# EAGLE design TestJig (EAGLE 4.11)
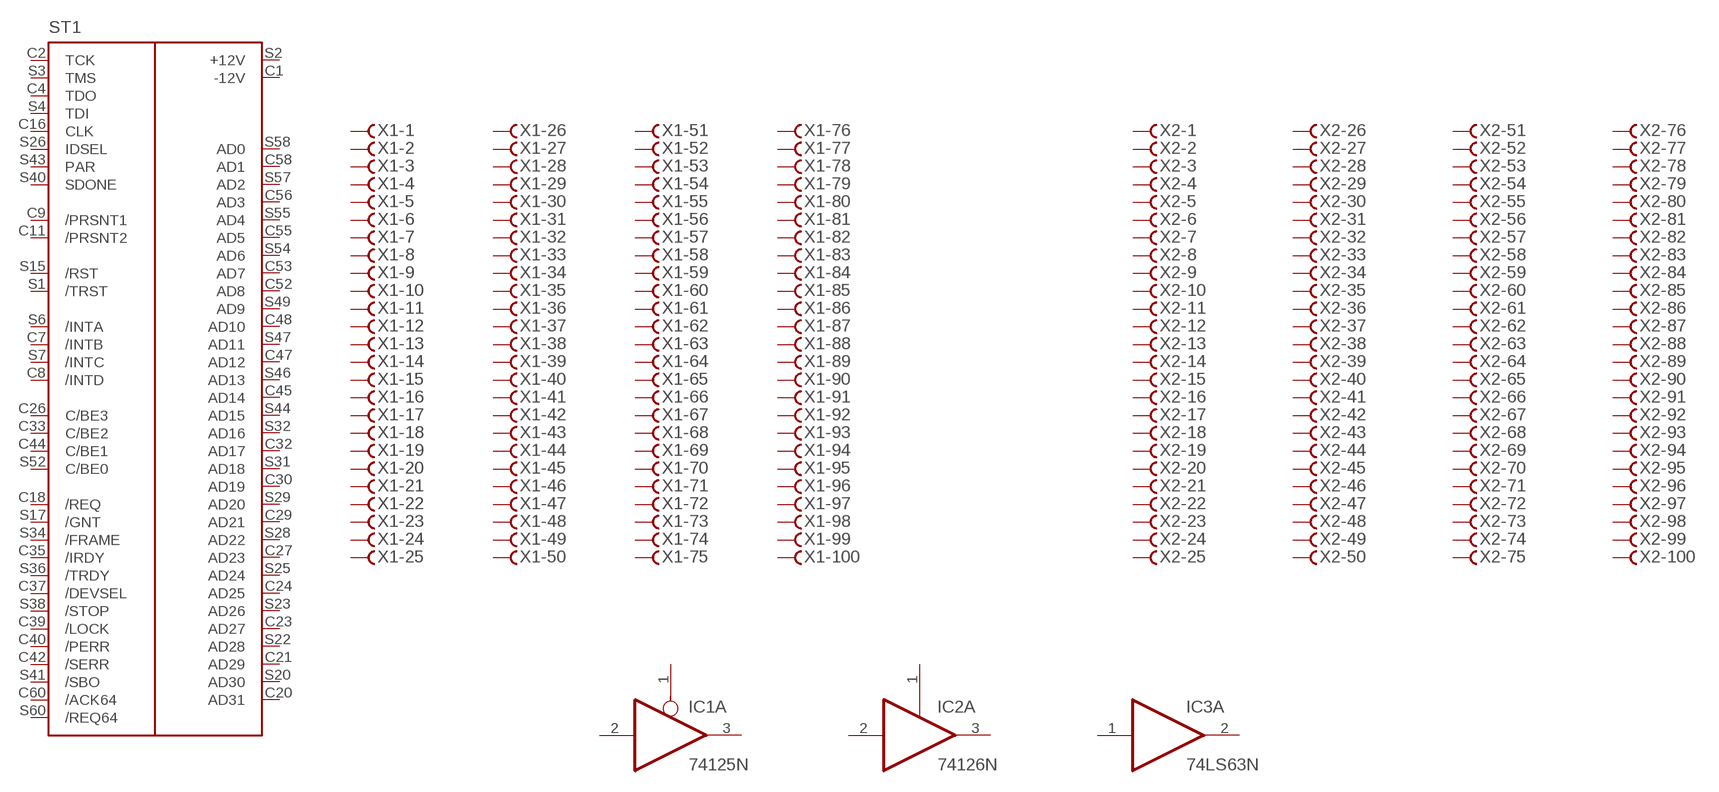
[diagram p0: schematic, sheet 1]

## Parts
IC1  74125N  [DIL14]
IC2  74126N  [DIL14]
IC3  74LS63N  [DIL14]
ST1  PCI2-SLOT  [PCI_BRD]
X1  HFR100RA  [HFR100RA]
X2  HXR100ST  [HXR100ST]
Unconnected: IC1.1(A:OE) IC1.2(A:I) IC1.3(A:O) IC1.4(B:OE) IC1.5(B:I) IC1.6(B:O) IC1.8(C:O) IC1.9(C:I) IC1.10(C:OE) IC1.11(D:O) IC1.12(D:I) IC1.13(D:OE) IC2.1(A:OE) IC2.2(A:I) IC2.3(A:O) IC2.4(B:OE) IC2.5(B:I) IC2.6(B:O) IC2.8(C:O) IC2.9(C:I) IC2.10(C:OE) IC2.11(D:O) IC2.12(D:I) IC2.13(D:OE) IC3.1(A:I) IC3.2(A:O) IC3.3(B:O) IC3.4(B:I) IC3.5(C:I) IC3.6(C:O) IC3.8(D:O) IC3.9(D:I) IC3.10(E:I) IC3.11(E:O) IC3.12(F:O) IC3.13(F:I) ST1.C2(TCK) ST1.C4(TDO) ST1.C7(/INTB) ST1.C8(/INTD) ST1.C9(/PRSNT1) ST1.C10(NC3) ST1.C11(/PRSNT2) ST1.C14(NC4) ST1.C16(CLK) ST1.C18(/REQ) ST1.C20(AD31) ST1.C21(AD29) ST1.C23(AD27) ST1.C24(AD25) ST1.C26(C/BE3) ST1.C27(AD23) ST1.C29(AD21) ST1.C30(AD19) ST1.C32(AD17) ST1.C33(C/BE2) ST1.C35(/IRDY) ST1.C37(/DEVSEL) ST1.C39(/LOCK) ST1.C40(/PERR) ST1.C42(/SERR) ST1.C44(C/BE1) ST1.C45(AD14) ST1.C47(AD12) ST1.C48(AD10) ST1.C52(AD8) ST1.C53(AD7) ST1.C55(AD5) ST1.C56(AD3) ST1.C58(AD1) ST1.C60(/ACK64) ST1.S1(/TRST) ST1.S3(TMS) ST1.S4(TDI) ST1.S6(/INTA) ST1.S7(/INTC) ST1.S9(NC0) ST1.S11(NC5) ST1.S14(NC1) ST1.S15(/RST) ST1.S17(/GNT) ST1.S19(NC2) ST1.S20(AD30) ST1.S22(AD28) ST1.S23(AD26) ST1.S25(AD24) ST1.S26(IDSEL) ST1.S28(AD22) ST1.S29(AD20) ST1.S31(AD18) ST1.S32(AD16) ST1.S34(/FRAME) ST1.S35(GND) ST1.S36(/TRDY) ST1.S38(/STOP) ST1.S39(+3,3V) ST1.S40(SDONE) ST1.S41(/SBO) ST1.S43(PAR) ST1.S44(AD15) ST1.S46(AD13) ST1.S47(AD11) ST1.S49(AD9) ST1.S52(C/BE0) ST1.S54(AD6) ST1.S55(AD4) ST1.S57(AD2) ST1.S58(AD0) ST1.S60(/REQ64) X1.1 X1.2 X1.3 X1.4 X1.5 X1.6 X1.7 X1.8 X1.9 X1.10 X1.11 X1.12 X1.13 X1.14 X1.15 X1.16 X1.17 X1.18 X1.19 X1.20 X1.21 X1.22 X1.23 X1.24 X1.25 X1.26 X1.27 X1.28 X1.29 X1.30 X1.31 X1.32 X1.33 X1.34 X1.35 X1.36 X1.37 X1.38 X1.39 X1.40 X1.41 X1.42 X1.43 X1.44 X1.45 X1.46 X1.47 X1.48 X1.49 X1.50 X1.51 X1.52 X1.53 X1.54 X1.55 X1.56 X1.57 X1.58 X1.59 X1.60 X1.61 X1.62 X1.63 X1.64 X1.65 X1.66 X1.67 X1.68 X1.69 X1.70 X1.71 X1.72 X1.73 X1.74 X1.75 X1.76 X1.77 X1.78 X1.79 X1.80 X1.81 X1.82 X1.83 X1.84 X1.85 X1.86 X1.87 X1.88 X1.89 X1.90 X1.91 X1.92 X1.93 X1.94 X1.95 X1.96 X1.97 X1.98 X1.99 X1.100 X2.1 X2.2 X2.3 X2.4 X2.5 X2.6 X2.7 X2.8 X2.9 X2.10 X2.11 X2.12 X2.13 X2.14 X2.15 X2.16 X2.17 X2.18 X2.19 X2.20 X2.21 X2.22 X2.23 X2.24 X2.25 X2.26 X2.27 X2.28 X2.29 X2.30 X2.31 X2.32 X2.33 X2.34 X2.35 X2.36 X2.37 X2.38 X2.39 X2.40 X2.41 X2.42 X2.43 X2.44 X2.45 X2.46 X2.47 X2.48 X2.49 X2.50 X2.51 X2.52 X2.53 X2.54 X2.55 X2.56 X2.57 X2.58 X2.59 X2.60 X2.61 X2.62 X2.63 X2.64 X2.65 X2.66 X2.67 X2.68 X2.69 X2.70 X2.71 X2.72 X2.73 X2.74 X2.75 X2.76 X2.77 X2.78 X2.79 X2.80 X2.81 X2.82 X2.83 X2.84 X2.85 X2.86 X2.87 X2.88 X2.89 X2.90 X2.91 X2.92 X2.93 X2.94 X2.95 X2.96 X2.97 X2.98 X2.99 X2.100

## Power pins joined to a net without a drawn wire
+3,3V: ST1.C25(+3,3V) ST1.C31(+3,3V) ST1.C36(+3,3V) ST1.C41(+3,3V) ST1.C43(+3,3V) ST1.C54(+3,3V) ST1.S21(+3,3V) ST1.S27(+3,3V) ST1.S33(+3,3V) ST1.S45(+3,3V) ST1.S53(+3,3V)
+5V: ST1.C5(+5V) ST1.C6(+5V) ST1.C19(+5V) ST1.C59(+5V) ST1.C61(+5V) ST1.C62(+5V) ST1.S5(+5V) ST1.S8(+5V) ST1.S10(+5V) ST1.S16(+5V) ST1.S59(+5V) ST1.S61(+5V) ST1.S62(+5V)
+12V: ST1.S2(+12V)
-12V: ST1.C1(-12V)
GND: IC1.7(P:GND) IC2.7(P:GND) IC3.7(P:GND) ST1.C3(GND) ST1.C12(GND) ST1.C13(GND) ST1.C15(GND) ST1.C17(GND) ST1.C22(GND) ST1.C28(GND) ST1.C34(GND) ST1.C38(GND) ST1.C46(GND) ST1.C49(GND) ST1.C57(GND) ST1.S12(GND) ST1.S13(GND) ST1.S18(GND) ST1.S24(GND) ST1.S30(GND) ST1.S37(GND) ST1.S42(GND) ST1.S48(GND) ST1.S56(GND)
VCC: IC1.14(P:VCC) IC2.14(P:VCC) IC3.14(P:VCC)

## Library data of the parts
IC1 = 74xx-us:74*125: Quad bus BUFFER, 3-state
IC2 = 74xx-us:74*126: Quad bus BUFFER, 3-state
IC3 = 74xx-us:74*63: Hex current sensing INTERFACE gate, totem pole
ST1 = con-pc:PCI2-SLOT: PCI BOARD SHORT
X1 = con-thomas-betts:HFR100RA: THOMAS&BETTS
X2 = con-thomas-betts:HXR100ST: THOMAS&BETTS

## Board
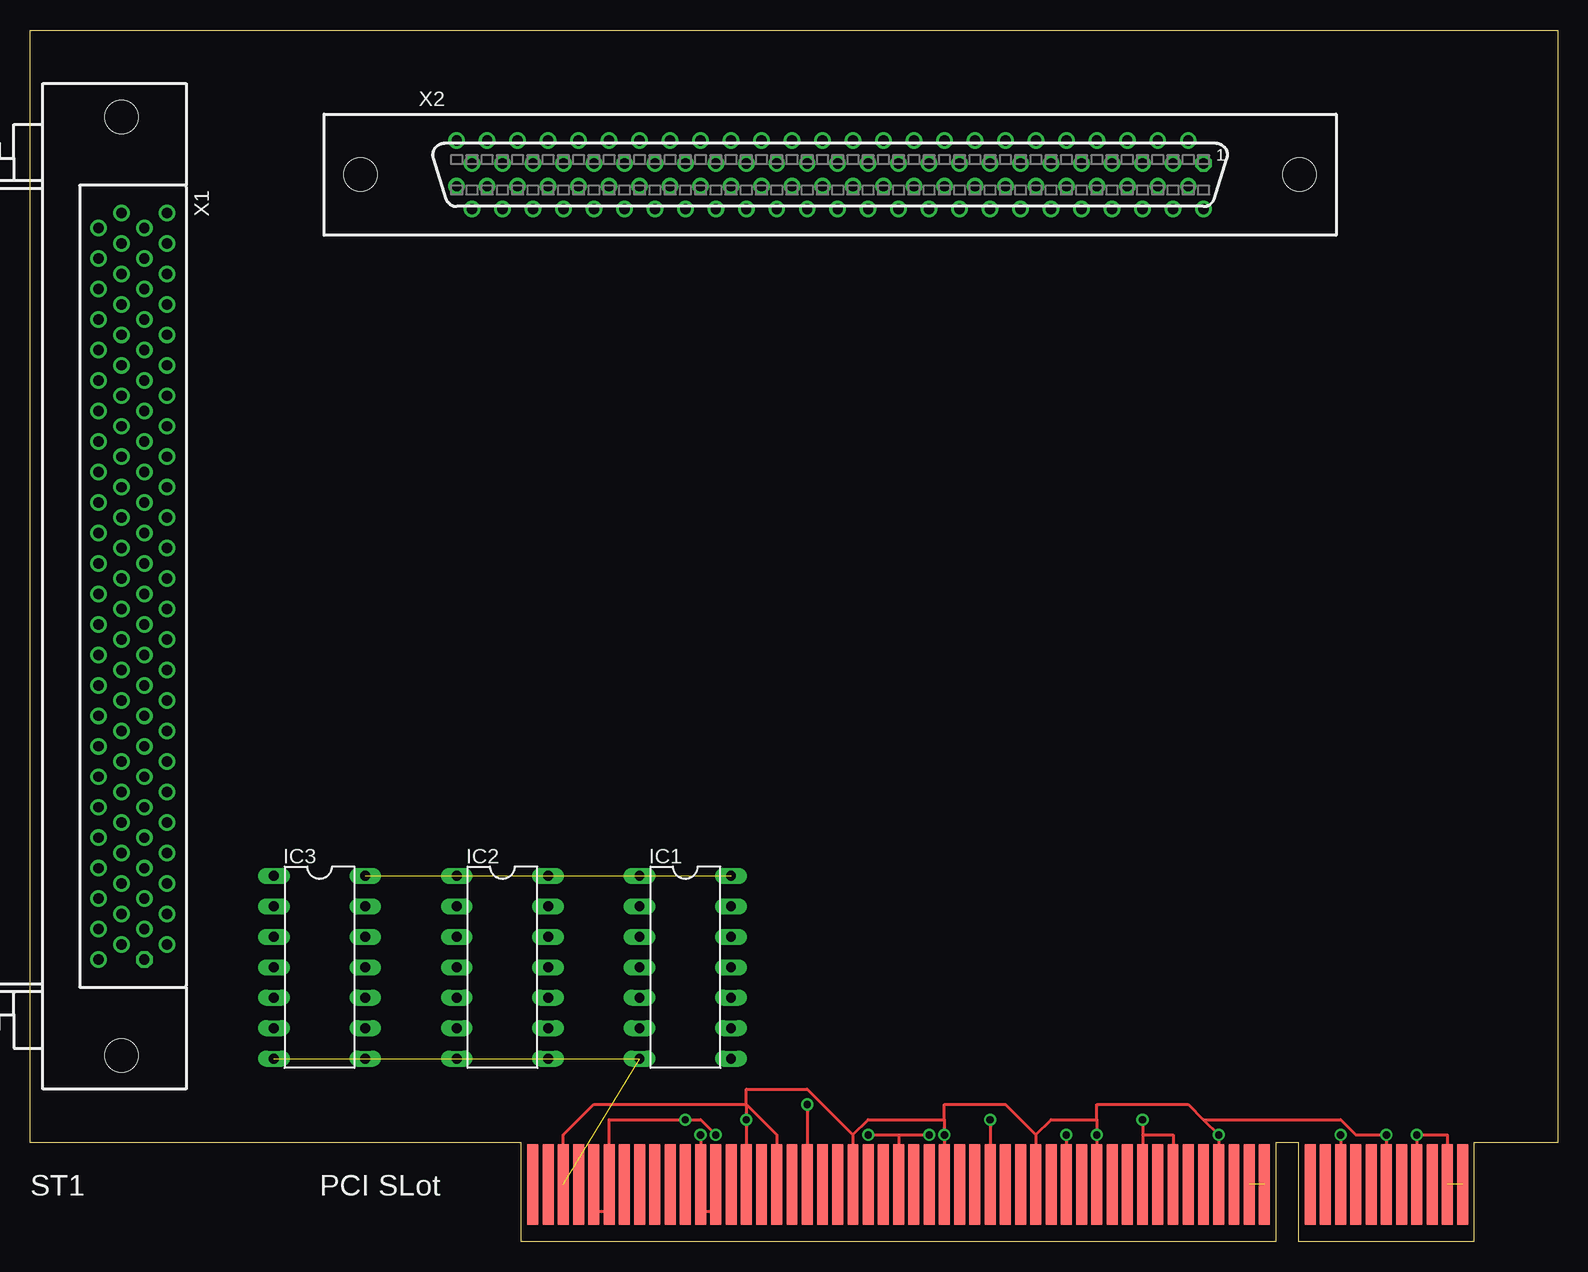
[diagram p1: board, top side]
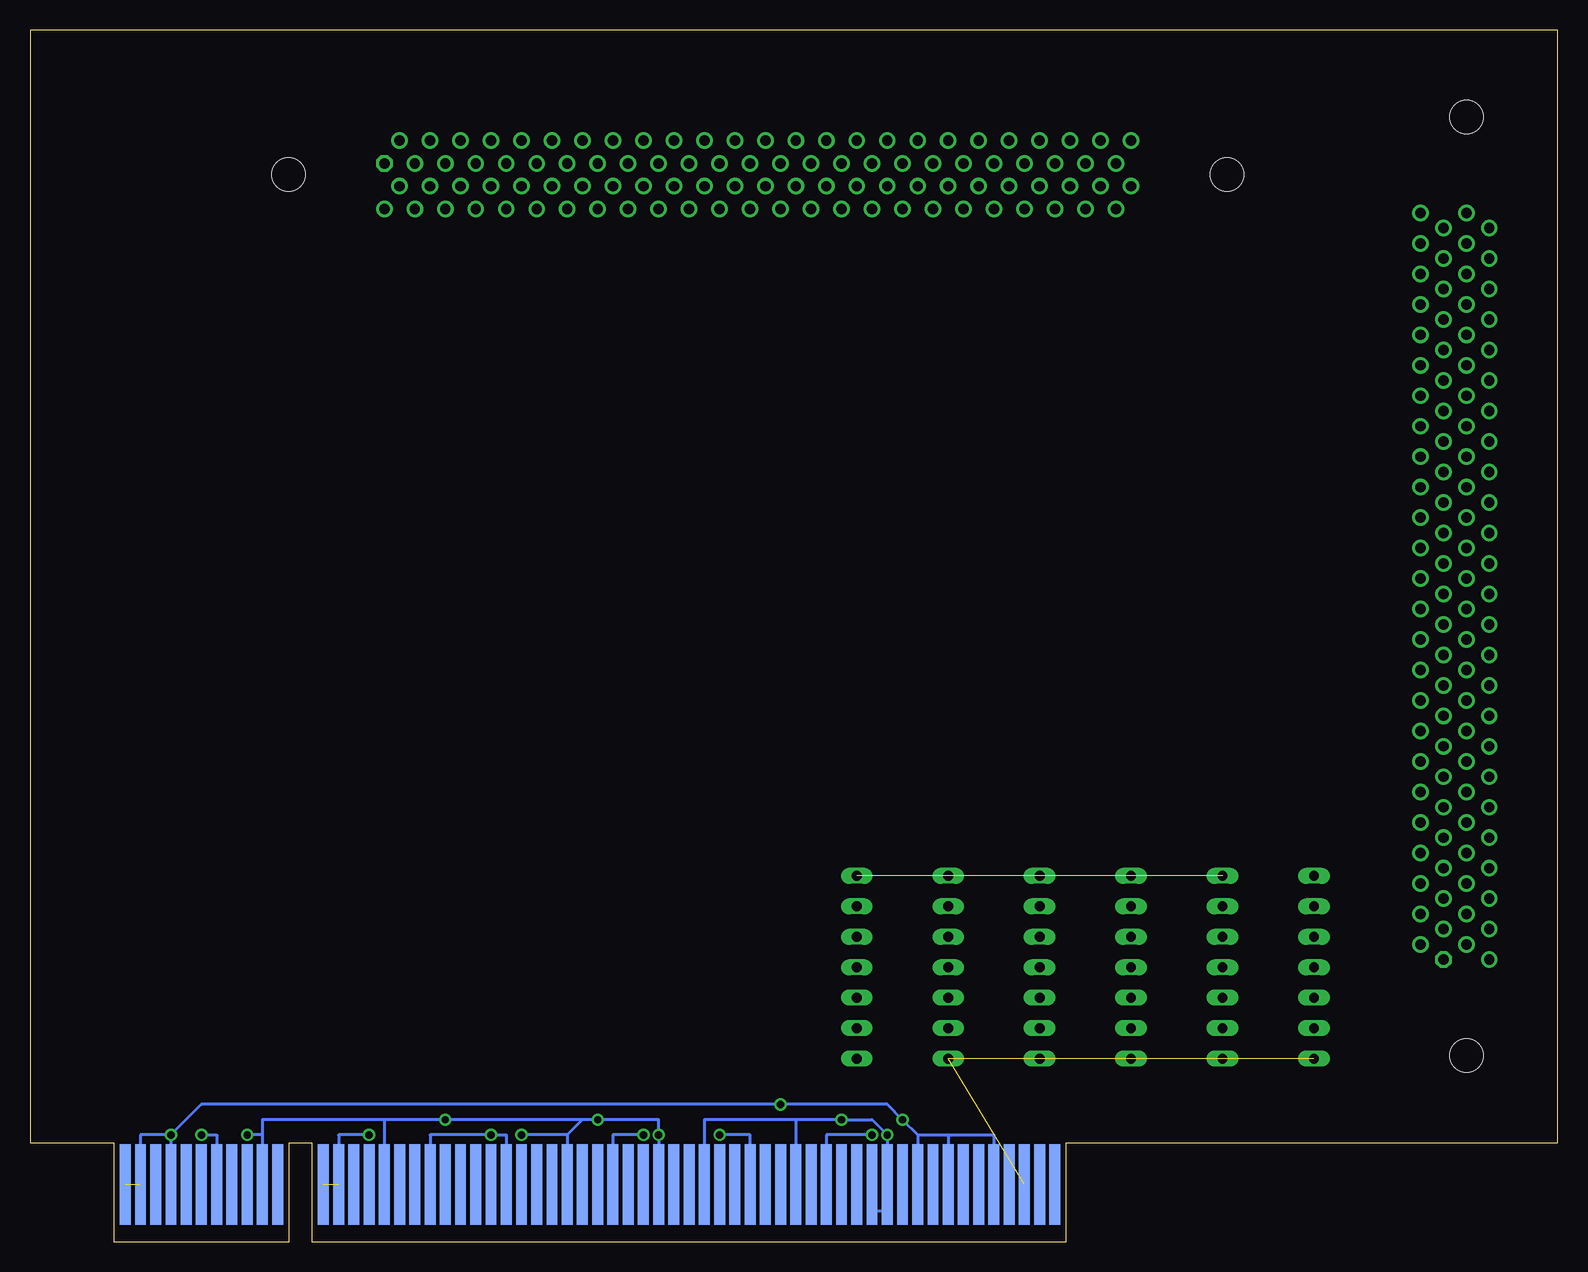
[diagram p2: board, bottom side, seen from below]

Size 127.32 x 100.97 mm. Coordinates in mm from the lower left corner, seen from the top.
Copper layers (1*16): Top 0.035mm / dielectric 1.5mm / Bottom 0.035mm
Design rules "10mils": minimum track width 10mil, minimum drill 24mil, track to track 10mil, track to pad 10mil, pad to pad 10mil, via to via 10mil, smd to smd 10mil, copper to edge 40mil, drill to drill 10mil, minimum pad ring 10mil, minimum via ring 8mil, stop-mask expansion 0mil, vias tented up to drill 0mil, thermal gap 10mil

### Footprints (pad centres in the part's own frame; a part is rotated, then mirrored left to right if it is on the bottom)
DIL14 = drill 0.813 long: 1 -7.62,-3.81; 2 -5.08,-3.81; 3 -2.54,-3.81; 4 0,-3.81; 5 2.54,-3.81; 6 5.08,-3.81; 7 7.62,-3.81; 8 7.62,3.81; 9 5.08,3.81; 10 2.54,3.81; 11 0,3.81; 12 -2.54,3.81; 13 -5.08,3.81; 14 -7.62,3.81
PCI_BRD = smd 0.91 x 6.7: C1 41.91,4.763; C2 43.18,4.763; C3 44.45,4.763; C4 45.72,4.763; C5 46.99,4.763; C6 48.26,4.763; C7 49.53,4.763; C8 50.8,4.763; C9 52.07,4.763; C10 53.34,4.763; C11 54.61,4.763; C12 55.88,4.763; C13 57.15,4.763; C14 58.42,4.763; C15 59.69,4.763; C16 60.96,4.763; C17 62.23,4.763; C18 63.5,4.763; C19 64.77,4.763; C20 66.04,4.763; C21 67.31,4.763; C22 68.58,4.763; C23 69.85,4.763; C24 71.12,4.763; C25 72.39,4.763; C26 73.66,4.763; C27 74.93,4.763; C28 76.2,4.763; C29 77.47,4.763; C30 78.74,4.763; C31 80.01,4.763; C32 81.28,4.763; C33 82.55,4.763; C34 83.82,4.763; C35 85.09,4.763; C36 86.36,4.763; C37 87.63,4.763; C38 88.9,4.763; C39 90.17,4.763; C40 91.44,4.763; C41 92.71,4.763; C42 93.98,4.763; C43 95.25,4.763; C44 96.52,4.763; C45 97.79,4.763; C46 99.06,4.763; C47 100.33,4.763; C48 101.6,4.763; C49 102.87,4.763; C52 106.68,4.763; C53 107.95,4.763; C54 109.22,4.763; C55 110.49,4.763; C56 111.76,4.763; C57 113.03,4.763; C58 114.3,4.763; C59 115.57,4.763; C60 116.84,4.763; C61 118.11,4.763; C62 119.38,4.763 | smd 0.91 x 6.7 bottom: S1 41.91,4.763; S2 43.18,4.763; S3 44.45,4.763; S4 45.72,4.763; S5 46.99,4.763; S6 48.26,4.763; S7 49.53,4.763; S8 50.8,4.763; S9 52.07,4.763; S10 53.34,4.763; S11 54.61,4.763; S12 55.88,4.763; S13 57.15,4.763; S14 58.42,4.763; S15 59.69,4.763; S16 60.96,4.763; S17 62.23,4.763; S18 63.5,4.763; S19 64.77,4.763; S20 66.04,4.763; S21 67.31,4.763; S22 68.58,4.763; S23 69.85,4.763; S24 71.12,4.763; S25 72.39,4.763; S26 73.66,4.763; S27 74.93,4.763; S28 76.2,4.763; S29 77.47,4.763; S30 78.74,4.763; S31 80.01,4.763; S32 81.28,4.763; S33 82.55,4.763; S34 83.82,4.763; S35 85.09,4.763; S36 86.36,4.763; S37 87.63,4.763; S38 88.9,4.763; S39 90.17,4.763; S40 91.44,4.763; S41 92.71,4.763; S42 93.98,4.763; S43 95.25,4.763; S44 96.52,4.763; S45 97.79,4.763; S46 99.06,4.763; S47 100.33,4.763; S48 101.6,4.763; S49 102.87,4.763; S52 106.68,4.763; S53 107.95,4.763; S54 109.22,4.763; S55 110.49,4.763; S56 111.76,4.763; S57 113.03,4.763; S58 114.3,4.763; S59 115.57,4.763; S60 116.84,4.763; S61 118.11,4.763; S62 119.38,4.763
HFR100RA = drill 0.864 octagon: 1 31.115,6.985 | drill 0.864 round: 2 29.845,8.89; 3 28.575,6.985; 4 27.305,8.89; 5 26.035,6.985; 6 24.765,8.89; 7 23.495,6.985; 8 22.225,8.89; 9 20.955,6.985; 10 19.685,8.89; 11 18.415,6.985; 12 17.145,8.89; 13 15.875,6.985; 14 14.605,8.89; 15 13.335,6.985; 16 12.065,8.89; 17 10.795,6.985; 18 9.525,8.89; 19 8.255,6.985; 20 6.985,8.89; 21 5.715,6.985; 22 4.445,8.89; 23 3.175,6.985; 24 1.905,8.89; 25 0.635,6.985; 26 -0.635,8.89; 27 -1.905,6.985; 28 -3.175,8.89; 29 -4.445,6.985; 30 -5.715,8.89; 31 -6.985,6.985; 32 -8.255,8.89; 33 -9.525,6.985; 34 -10.795,8.89; 35 -12.065,6.985; 36 -13.335,8.89; 37 -14.605,6.985; 38 -15.875,8.89; 39 -17.145,6.985; 40 -18.415,8.89; 41 -19.685,6.985; 42 -20.955,8.89; 43 -22.225,6.985; 44 -23.495,8.89; 45 -24.765,6.985; 46 -26.035,8.89; 47 -27.305,6.985; 48 -28.575,8.89; 49 -29.845,6.985; 50 -31.115,8.89; 51 31.115,3.175; 52 29.845,5.08; 53 28.575,3.175; 54 27.305,5.08; 55 26.035,3.175; 56 24.765,5.08; 57 23.495,3.175; 58 22.225,5.08; 59 20.955,3.175; 60 19.685,5.08; 61 18.415,3.175; 62 17.145,5.08; 63 15.875,3.175; 64 14.605,5.08; 65 13.335,3.175; 66 12.065,5.08; 67 10.795,3.175; 68 9.525,5.08; 69 8.255,3.175; 70 6.985,5.08; 71 5.715,3.175; 72 4.445,5.08; 73 3.175,3.175; 74 1.905,5.08; 75 0.635,3.175; 76 -0.635,5.08; 77 -1.905,3.175; 78 -3.175,5.08; 79 -4.445,3.175; 80 -5.715,5.08; 81 -6.985,3.175; 82 -8.255,5.08; 83 -9.525,3.175; 84 -10.795,5.08; 85 -12.065,3.175; 86 -13.335,5.08; 87 -14.605,3.175; 88 -15.875,5.08; 89 -17.145,3.175; 90 -18.415,5.08; 91 -19.685,3.175; 92 -20.955,5.08; 93 -22.225,3.175; 94 -23.495,5.08; 95 -24.765,3.175; 96 -26.035,5.08; 97 -27.305,3.175; 98 -28.575,5.08; 99 -29.845,3.175; 100 -31.115,5.08 | hole 2.769: 39.116,5.08; -39.116,5.08
HXR100ST = drill 0.864 octagon: 1 31.115,0.953 | drill 0.864 round: 2 29.845,2.857; 3 28.575,0.953; 4 27.305,2.857; 5 26.035,0.953; 6 24.765,2.857; 7 23.495,0.953; 8 22.225,2.857; 9 20.955,0.953; 10 19.685,2.857; 11 18.415,0.953; 12 17.145,2.857; 13 15.875,0.953; 14 14.605,2.857; 15 13.335,0.953; 16 12.065,2.857; 17 10.795,0.953; 18 9.525,2.857; 19 8.255,0.953; 20 6.985,2.857; 21 5.715,0.953; 22 4.445,2.857; 23 3.175,0.953; 24 1.905,2.857; 25 0.635,0.953; 26 -0.635,2.857; 27 -1.905,0.953; 28 -3.175,2.857; 29 -4.445,0.953; 30 -5.715,2.857; 31 -6.985,0.953; 32 -8.255,2.857; 33 -9.525,0.953; 34 -10.795,2.857; 35 -12.065,0.953; 36 -13.335,2.857; 37 -14.605,0.953; 38 -15.875,2.857; 39 -17.145,0.953; 40 -18.415,2.857; 41 -19.685,0.953; 42 -20.955,2.857; 43 -22.225,0.953; 44 -23.495,2.857; 45 -24.765,0.953; 46 -26.035,2.857; 47 -27.305,0.953; 48 -28.575,2.857; 49 -29.845,0.953; 50 -31.115,2.857; 51 31.115,-2.857; 52 29.845,-0.953; 53 28.575,-2.857; 54 27.305,-0.953; 55 26.035,-2.857; 56 24.765,-0.953; 57 23.495,-2.857; 58 22.225,-0.953; 59 20.955,-2.857; 60 19.685,-0.953; 61 18.415,-2.857; 62 17.145,-0.953; 63 15.875,-2.857; 64 14.605,-0.953; 65 13.335,-2.857; 66 12.065,-0.953; 67 10.795,-2.857; 68 9.525,-0.953; 69 8.255,-2.857; 70 6.985,-0.953; 71 5.715,-2.857; 72 4.445,-0.953; 73 3.175,-2.857; 74 1.905,-0.953; 75 0.635,-2.857; 76 -0.635,-0.953; 77 -1.905,-2.857; 78 -3.175,-0.953; 79 -4.445,-2.857; 80 -5.715,-0.953; 81 -6.985,-2.857; 82 -8.255,-0.953; 83 -9.525,-2.857; 84 -10.795,-0.953; 85 -12.065,-2.857; 86 -13.335,-0.953; 87 -14.605,-2.857; 88 -15.875,-0.953; 89 -17.145,-2.857; 90 -18.415,-0.953; 91 -19.685,-2.857; 92 -20.955,-0.953; 93 -22.225,-2.857; 94 -23.495,-0.953; 95 -24.765,-2.857; 96 -26.035,-0.953; 97 -27.305,-2.857; 98 -28.575,-0.953; 99 -29.845,-2.857; 100 -31.115,-0.953 | hole 2.769: 39.116,0.013; -39.116,0.013

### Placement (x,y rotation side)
IC1  54.61,22.86 270 top
IC2  39.37,22.86 270 top
IC3  24.13,22.86 270 top
ST1  0,0 0 top
X1  2.54,54.61 270 top
X2  66.67,88.9 0 top

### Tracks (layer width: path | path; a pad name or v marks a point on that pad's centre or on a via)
+3,3V  (via drill 0.61)
  Top 0.254: v69.85,8.89 72.39,8.89 | 72.39,8.89 72.39,7.62 ST1.C25 | 92.71,8.89 92.71,7.62 ST1.C41 | 92.71,8.89 95.25,8.89 95.25,7.62 ST1.C43 | v80.01,10.16 80.01,7.62 ST1.C31 | v86.36,8.89 86.36,7.62 ST1.C36 | v109.22,8.89 109.22,7.62 ST1.C54 | v92.71,10.16 92.71,8.89 | 72.39,8.89 v74.93,8.89
  Bottom 0.254: v69.85,8.89 67.31,8.89 67.31,7.62 ST1.S21 | 81.28,10.16 v80.01,10.16 74.93,10.16 v74.93,8.89 74.93,7.62 ST1.S27 | 81.28,10.16 82.55,8.89 | 82.55,8.89 82.55,7.62 ST1.S33 | 82.55,8.89 v86.36,8.89 | 97.79,10.16 97.79,7.62 ST1.S45 | 81.28,10.16 v92.71,10.16 97.79,10.16 | 107.95,8.89 107.95,10.16 97.79,10.16 | 107.95,8.89 107.95,7.62 ST1.S53 | 107.95,8.89 v109.22,8.89
+5V  (via drill 0.61)  (2 unrouted)
  Top 0.254: ST1.C5 46.99,2.54 48.26,2.54 ST1.C6 48.26,7.62 48.26,10.16 v54.61,10.16 55.88,10.16 v57.15,8.89 | ST1.C59 115.57,7.62 v115.57,8.89 118.11,8.89 118.11,7.62 ST1.C61 | v64.77,11.43 64.77,7.62 ST1.C19
  Bottom 0.254: v57.15,8.89 60.96,8.89 60.96,7.62 ST1.S16 | v115.57,8.89 115.57,7.62 ST1.C59 | v115.57,8.89 118.11,8.89 118.11,7.62 ST1.C61 | 50.8,8.89 46.99,8.89 46.99,7.62 ST1.C5 | 50.8,8.89 50.8,7.62 ST1.S8 | 53.34,8.89 53.34,7.62 ST1.S10 | 53.34,8.89 50.8,8.89 | 53.34,8.89 v54.61,10.16 55.88,11.43 v64.77,11.43 113.03,11.43 v115.57,8.89
GND  (via drill 0.61)  (4 unrouted)
  Top 0.254: ST1.C57 113.03,7.62 v113.03,8.89 110.49,8.89 109.22,10.16 97.79,10.16 | 83.82,8.89 83.82,7.62 ST1.C34 | 83.82,8.89 85.09,10.16 88.9,10.16 | 88.9,10.16 v88.9,8.89 88.9,7.62 ST1.C38 | 97.79,10.16 96.52,11.43 88.9,11.43 88.9,10.16 | 97.79,10.16 v99.06,8.89 99.06,7.62 ST1.C46 | ST1.C13 57.15,2.54 55.88,2.54 ST1.C12 55.88,7.62 v55.88,8.89 | 68.58,8.89 68.58,7.62 ST1.C22 | 68.58,8.89 69.85,10.16 76.2,10.16 | 76.2,10.16 v76.2,8.89 76.2,7.62 ST1.C28 | 59.69,11.43 46.99,11.43 44.45,8.89 44.45,7.62 ST1.C3 | 59.69,11.43 v59.69,10.16 59.69,7.62 ST1.C15 | 59.69,11.43 62.23,8.89 62.23,7.62 ST1.C17 | 68.58,8.89 64.77,12.7 59.69,12.7 59.69,11.43 | 83.82,8.89 81.28,11.43 76.2,11.43 76.2,10.16
  Bottom 0.254: ST1.S37 87.63,7.62 87.63,8.89 v88.9,8.89 93.98,8.89 93.98,7.62 ST1.S42 | v113.03,8.89 111.76,8.89 111.76,7.62 ST1.S56 | v99.06,8.89 101.6,8.89 101.6,7.62 ST1.S48 | ST1.C13 57.15,2.54 55.88,2.54 ST1.C12 55.88,7.62 v55.88,8.89 57.15,10.16 v59.69,10.16 63.5,10.16 | 63.5,10.16 63.5,7.62 ST1.S18 | 63.5,10.16 71.12,10.16 71.12,7.62 ST1.S24 | v76.2,8.89 78.74,8.89 78.74,7.62 ST1.S30
VCC  (2 unrouted)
